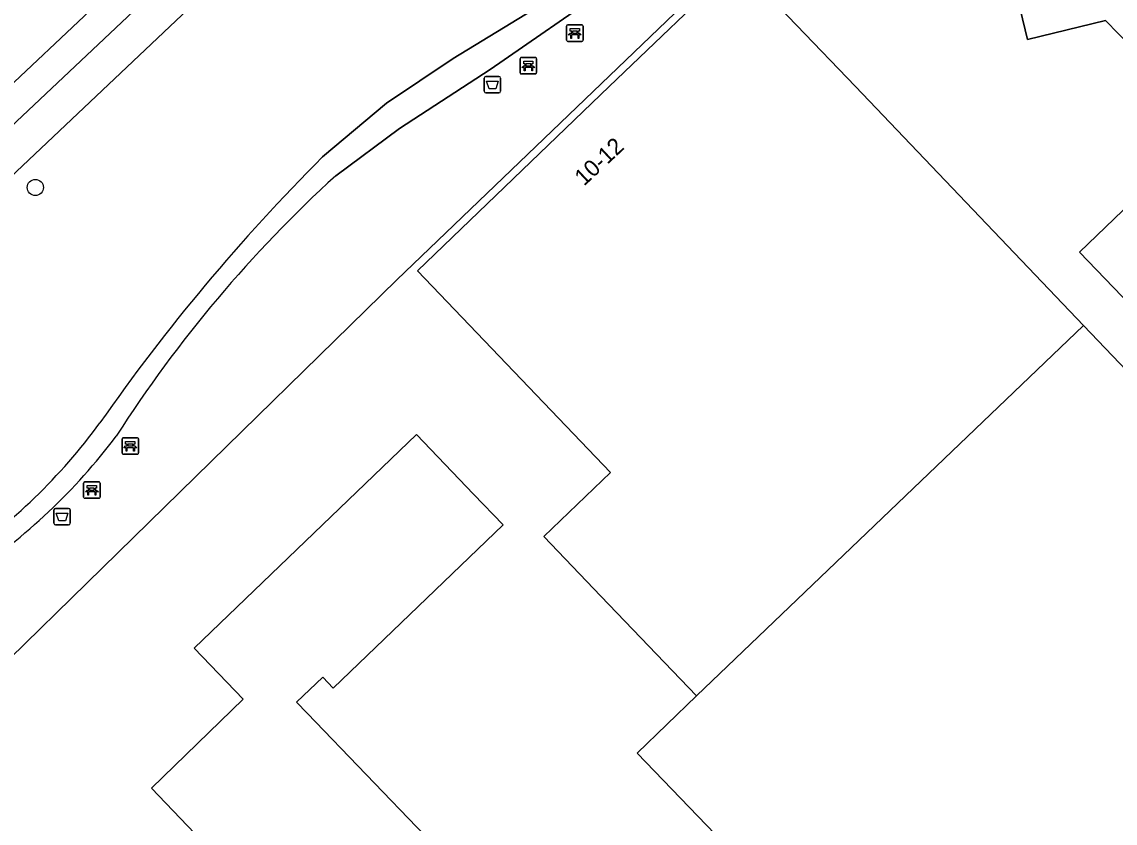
# Model space of a CAD drawing. Extents: x 156702 to 158052, y 387630 to 388992.
# Drawn here: x 157527.1 to 157593.4, y 388205.4 to 388253.9 of the extents above; entities that cross this region are included whole.
import ezdxf

# ---------------------------------------------------------------- set-up
doc = ezdxf.new("R2010")
doc.units = 0
for name, color, linetype in [('IMGEO_Afvalbak', 7, 'Continuous'), ('IMGEO_Bank', 7, 'Continuous'), ('IMGEO_Boom', 7, 'Continuous'), ('IMGEO_Erf', 7, 'Continuous'), ('IMGEO_Groenvoorziening', 7, 'Continuous'), ('IMGEO_Hek', 7, 'Continuous'), ('IMGEO_Pand', 7, 'Continuous'), ('IMGEO_Pand_nummerreeks', 7, 'Continuous'), ('IMGEO_Parkeervlak_open', 7, 'Continuous'), ('IMGEO_Voetpad_halfverhard', 7, 'Continuous'), ('IMGEO_Voetpad_open', 7, 'Continuous')]:
    doc.layers.add(name, color=color, linetype=linetype)

msp = doc.modelspace()

# ---------------------------------------------------------------- linework, layer by layer
at = {"layer": 'IMGEO_Afvalbak'}
for p, q in [((157555.123, 388249.714), (157555.123, 388250.514)), ((157555.123, 388250.514), (157555.123, 388249.714)), ((157555.223, 388250.614), (157556.013, 388250.614)), ((157556.013, 388250.614), (157555.223, 388250.614)), ((157556.113, 388250.514), (157556.113, 388249.714)), ((157556.113, 388249.714), (157556.113, 388250.514)), ((157556.013, 388249.614), (157555.223, 388249.614)), ((157555.223, 388249.614), (157556.013, 388249.614)), ((157529.032, 388223.535), (157529.032, 388224.335)), ((157529.032, 388224.335), (157529.032, 388223.535)), ((157529.132, 388224.435), (157529.922, 388224.435)), ((157529.922, 388224.435), (157529.132, 388224.435)), ((157530.022, 388224.335), (157530.022, 388223.535)), ((157530.022, 388223.535), (157530.022, 388224.335)), ((157529.922, 388223.435), (157529.132, 388223.435)), ((157529.132, 388223.435), (157529.922, 388223.435))]:
    msp.add_line(p, q, dxfattribs=at)
for points in [[(157555.266, 388250.328), (157555.97, 388250.328), (157555.821, 388249.858), (157555.415, 388249.858), (157555.266, 388250.328)], [(157529.175, 388224.149), (157529.879, 388224.149), (157529.73, 388223.679), (157529.324, 388223.679), (157529.175, 388224.149)]]:
    msp.add_lwpolyline(points, dxfattribs=at)
for centre, start, end in [((157555.223, 388250.514), 90, 180), ((157555.223, 388250.514), 90, 180), ((157556.013, 388250.514), 0, 90), ((157556.013, 388250.514), 360, 90), ((157555.223, 388249.714), 180, 270), ((157555.223, 388249.714), 180, 270), ((157556.013, 388249.714), 270, 0), ((157556.013, 388249.714), 270, 0), ((157529.132, 388224.335), 90, 180), ((157529.132, 388224.335), 90, 180), ((157529.922, 388224.335), 0, 90), ((157529.922, 388224.335), 360, 90), ((157529.132, 388223.535), 180, 270), ((157529.132, 388223.535), 180, 270), ((157529.922, 388223.535), 270, 0), ((157529.922, 388223.535), 270, 0)]:
    msp.add_arc(centre, 0.1, start, end, dxfattribs=at)
at = {"layer": 'IMGEO_Bank'}
for p, q in [((157560.191, 388253.742), (157561.032, 388253.742)), ((157561.032, 388253.742), (157560.191, 388253.742)), ((157560.116, 388252.817), (157560.116, 388253.658)), ((157560.116, 388253.658), (157560.116, 388252.817)), ((157560.813, 388253.14), (157560.42, 388253.14)), ((157560.425, 388253.248), (157560.425, 388253.354)), ((157560.469, 388253.354), (157560.469, 388253.248)), ((157560.757, 388253.36), (157560.475, 388253.36)), ((157560.475, 388253.242), (157560.757, 388253.242)), ((157560.763, 388253.248), (157560.763, 388253.354)), ((157560.807, 388253.354), (157560.807, 388253.248)), ((157561.116, 388253.667), (157561.116, 388252.826)), ((157561.116, 388252.826), (157561.116, 388253.667)), ((157561.041, 388252.742), (157560.2, 388252.742)), ((157560.2, 388252.742), (157561.041, 388252.742)), ((157557.374, 388251.765), (157558.215, 388251.765)), ((157558.215, 388251.765), (157557.374, 388251.765)), ((157557.299, 388250.84), (157557.299, 388251.681)), ((157557.299, 388251.681), (157557.299, 388250.84)), ((157557.996, 388251.163), (157557.603, 388251.163)), ((157557.608, 388251.271), (157557.608, 388251.377)), ((157557.652, 388251.377), (157557.652, 388251.271)), ((157557.94, 388251.383), (157557.658, 388251.383)), ((157557.658, 388251.265), (157557.94, 388251.265)), ((157557.946, 388251.271), (157557.946, 388251.377)), ((157557.99, 388251.377), (157557.99, 388251.271)), ((157558.299, 388251.69), (157558.299, 388250.849)), ((157558.299, 388250.849), (157558.299, 388251.69)), ((157558.224, 388250.765), (157557.383, 388250.765)), ((157557.383, 388250.765), (157558.224, 388250.765)), ((157533.163, 388227.79), (157533.163, 388228.631)), ((157533.163, 388228.631), (157533.163, 388227.79)), ((157533.238, 388228.715), (157534.079, 388228.715)), ((157534.079, 388228.715), (157533.238, 388228.715)), ((157534.163, 388228.64), (157534.163, 388227.799)), ((157534.163, 388227.799), (157534.163, 388228.64)), ((157533.86, 388228.113), (157533.467, 388228.113)), ((157533.472, 388228.221), (157533.472, 388228.327)), ((157533.516, 388228.327), (157533.516, 388228.221)), ((157533.804, 388228.333), (157533.522, 388228.333)), ((157533.522, 388228.215), (157533.804, 388228.215)), ((157533.81, 388228.221), (157533.81, 388228.327)), ((157533.854, 388228.327), (157533.854, 388228.221)), ((157534.088, 388227.715), (157533.247, 388227.715)), ((157533.247, 388227.715), (157534.088, 388227.715)), ((157530.835, 388225.117), (157530.835, 388225.958)), ((157530.835, 388225.958), (157530.835, 388225.117)), ((157530.91, 388226.042), (157531.751, 388226.042)), ((157531.751, 388226.042), (157530.91, 388226.042)), ((157531.835, 388225.967), (157531.835, 388225.126)), ((157531.835, 388225.126), (157531.835, 388225.967)), ((157531.532, 388225.44), (157531.139, 388225.44)), ((157531.144, 388225.548), (157531.144, 388225.654)), ((157531.188, 388225.654), (157531.188, 388225.548)), ((157531.476, 388225.66), (157531.194, 388225.66)), ((157531.194, 388225.542), (157531.476, 388225.542)), ((157531.482, 388225.548), (157531.482, 388225.654)), ((157531.526, 388225.654), (157531.526, 388225.548)), ((157531.76, 388225.042), (157530.919, 388225.042)), ((157530.919, 388225.042), (157531.76, 388225.042))]:
    msp.add_line(p, q, dxfattribs=at)
for points in [[(157560.363, 388253.14), (157560.221, 388253.14), (157560.333, 388253.242), (157560.419, 388253.242)], [(157560.419, 388253.36), (157560.333, 388253.36), (157560.333, 388253.521), (157560.896, 388253.521), (157560.896, 388253.36), (157560.813, 388253.36)], [(157560.413, 388253.133), (157560.413, 388252.926), (157560.37, 388252.926), (157560.37, 388253.133)], [(157560.813, 388253.242), (157560.896, 388253.242), (157561.008, 388253.14), (157560.869, 388253.14)], [(157560.863, 388253.133), (157560.863, 388252.926), (157560.819, 388252.926), (157560.819, 388253.133)], [(157557.546, 388251.163), (157557.404, 388251.163), (157557.516, 388251.265), (157557.602, 388251.265)], [(157557.602, 388251.383), (157557.516, 388251.383), (157557.516, 388251.544), (157558.079, 388251.544), (157558.079, 388251.383), (157557.996, 388251.383)], [(157557.596, 388251.156), (157557.596, 388250.949), (157557.553, 388250.949), (157557.553, 388251.156)], [(157557.996, 388251.265), (157558.079, 388251.265), (157558.191, 388251.163), (157558.052, 388251.163)], [(157558.046, 388251.156), (157558.046, 388250.949), (157558.002, 388250.949), (157558.002, 388251.156)], [(157533.41, 388228.113), (157533.268, 388228.113), (157533.38, 388228.215), (157533.466, 388228.215)], [(157533.466, 388228.333), (157533.38, 388228.333), (157533.38, 388228.494), (157533.943, 388228.494), (157533.943, 388228.333), (157533.86, 388228.333)], [(157533.46, 388228.106), (157533.46, 388227.899), (157533.417, 388227.899), (157533.417, 388228.106)], [(157533.86, 388228.215), (157533.943, 388228.215), (157534.055, 388228.113), (157533.916, 388228.113)], [(157533.91, 388228.106), (157533.91, 388227.899), (157533.866, 388227.899), (157533.866, 388228.106)], [(157531.082, 388225.44), (157530.94, 388225.44), (157531.052, 388225.542), (157531.138, 388225.542)], [(157531.138, 388225.66), (157531.052, 388225.66), (157531.052, 388225.821), (157531.615, 388225.821), (157531.615, 388225.66), (157531.532, 388225.66)], [(157531.132, 388225.433), (157531.132, 388225.226), (157531.089, 388225.226), (157531.089, 388225.433)], [(157531.532, 388225.542), (157531.615, 388225.542), (157531.727, 388225.44), (157531.588, 388225.44)], [(157531.582, 388225.433), (157531.582, 388225.226), (157531.538, 388225.226), (157531.538, 388225.433)]]:
    msp.add_lwpolyline(points, dxfattribs=at)
for centre, radius, start, end in [((157560.194, 388253.664), 0.0779, 92.4484, 184.28452), ((157560.194, 388253.664), 0.0779, 92.4484, 184.28452), ((157561.038, 388253.664), 0.0779, 2.4484, 94.28452), ((157561.038, 388253.664), 0.0779, 2.4484, 94.28452), ((157560.363, 388253.133), 0.00671, 2.89567, 87.10433), ((157560.42, 388253.133), 0.00671, 92.89567, 177.10433), ((157560.418, 388253.353), 0.00671, 2.89567, 87.10433), ((157560.418, 388253.249), 0.00671, 272.89567, 357.10433), ((157560.475, 388253.353), 0.00671, 92.89567, 177.10433), ((157560.475, 388253.249), 0.00671, 182.89567, 267.10433), ((157560.757, 388253.353), 0.00671, 2.89567, 87.10433), ((157560.757, 388253.249), 0.00671, 272.89567, 357.10433), ((157560.814, 388253.353), 0.00671, 92.89567, 177.10433), ((157560.814, 388253.249), 0.00671, 182.89567, 267.10433), ((157560.812, 388253.133), 0.00671, 2.89567, 87.10433), ((157560.869, 388253.133), 0.00671, 92.89567, 177.10433), ((157560.194, 388252.82), 0.0779, 182.4484, 274.28452), ((157560.194, 388252.82), 0.0779, 182.4484, 274.28452), ((157561.038, 388252.82), 0.0779, 272.4484, 4.28452), ((157561.038, 388252.82), 0.0779, 272.4484, 4.28452), ((157557.377, 388251.687), 0.0779, 92.4484, 184.28452), ((157557.377, 388251.687), 0.0779, 92.4484, 184.28452), ((157558.221, 388251.687), 0.0779, 2.4484, 94.28452), ((157558.221, 388251.687), 0.0779, 2.4484, 94.28452), ((157557.546, 388251.156), 0.00671, 2.89567, 87.10433), ((157557.603, 388251.156), 0.00671, 92.89567, 177.10433), ((157557.601, 388251.376), 0.00671, 2.89567, 87.10433), ((157557.601, 388251.272), 0.00671, 272.89567, 357.10433), ((157557.658, 388251.376), 0.00671, 92.89567, 177.10433), ((157557.658, 388251.272), 0.00671, 182.89567, 267.10433), ((157557.94, 388251.376), 0.00671, 2.89567, 87.10433), ((157557.94, 388251.272), 0.00671, 272.89567, 357.10433), ((157557.997, 388251.376), 0.00671, 92.89567, 177.10433), ((157557.997, 388251.272), 0.00671, 182.89567, 267.10433), ((157557.995, 388251.156), 0.00671, 2.89567, 87.10433), ((157558.052, 388251.156), 0.00671, 92.89567, 177.10433), ((157557.377, 388250.843), 0.0779, 182.4484, 274.28452), ((157557.377, 388250.843), 0.0779, 182.4484, 274.28452), ((157558.221, 388250.843), 0.0779, 272.4484, 4.28452), ((157558.221, 388250.843), 0.0779, 272.4484, 4.28452), ((157533.241, 388228.637), 0.0779, 92.4484, 184.28452), ((157533.241, 388228.637), 0.0779, 92.4484, 184.28452), ((157534.085, 388228.637), 0.0779, 2.4484, 94.28452), ((157534.085, 388228.637), 0.0779, 2.4484, 94.28452), ((157533.41, 388228.106), 0.00671, 2.89567, 87.10433), ((157533.467, 388228.106), 0.00671, 92.89567, 177.10433), ((157533.465, 388228.326), 0.00671, 2.89567, 87.10433), ((157533.465, 388228.222), 0.00671, 272.89567, 357.10433), ((157533.522, 388228.326), 0.00671, 92.89567, 177.10433), ((157533.522, 388228.222), 0.00671, 182.89567, 267.10433), ((157533.804, 388228.326), 0.00671, 2.89567, 87.10433), ((157533.804, 388228.222), 0.00671, 272.89567, 357.10433), ((157533.861, 388228.326), 0.00671, 92.89567, 177.10433), ((157533.861, 388228.222), 0.00671, 182.89567, 267.10433), ((157533.859, 388228.106), 0.00671, 2.89567, 87.10433), ((157533.916, 388228.106), 0.00671, 92.89567, 177.10433), ((157533.241, 388227.793), 0.0779, 182.4484, 274.28452), ((157533.241, 388227.793), 0.0779, 182.4484, 274.28452), ((157534.085, 388227.793), 0.0779, 272.4484, 4.28452), ((157534.085, 388227.793), 0.0779, 272.4484, 4.28452), ((157530.913, 388225.964), 0.0779, 92.4484, 184.28452), ((157530.913, 388225.964), 0.0779, 92.4484, 184.28452), ((157531.757, 388225.964), 0.0779, 2.4484, 94.28452), ((157531.757, 388225.964), 0.0779, 2.4484, 94.28452), ((157531.082, 388225.433), 0.00671, 2.89567, 87.10433), ((157531.139, 388225.433), 0.00671, 92.89567, 177.10433), ((157531.137, 388225.653), 0.00671, 2.89567, 87.10433), ((157531.137, 388225.549), 0.00671, 272.89567, 357.10433), ((157531.194, 388225.653), 0.00671, 92.89567, 177.10433), ((157531.194, 388225.549), 0.00671, 182.89567, 267.10433), ((157531.476, 388225.653), 0.00671, 2.89567, 87.10433), ((157531.476, 388225.549), 0.00671, 272.89567, 357.10433), ((157531.533, 388225.653), 0.00671, 92.89567, 177.10433), ((157531.533, 388225.549), 0.00671, 182.89567, 267.10433), ((157531.531, 388225.433), 0.00671, 2.89567, 87.10433), ((157531.588, 388225.433), 0.00671, 92.89567, 177.10433), ((157530.913, 388225.12), 0.0779, 182.4484, 274.28452), ((157530.913, 388225.12), 0.0779, 182.4484, 274.28452), ((157531.757, 388225.12), 0.0779, 272.4484, 4.28452), ((157531.757, 388225.12), 0.0779, 272.4484, 4.28452)]:
    msp.add_arc(centre, radius, start, end, dxfattribs=at)
at = {"layer": 'IMGEO_Boom'}
msp.add_circle((157527.908, 388243.888), 0.489, dxfattribs=at)
at = {"layer": 'IMGEO_Erf'}
msp.add_lwpolyline([(157658.038, 388128.535), (157625.935, 388161.878), (157607.282, 388185.621), (157608.898, 388187.206), (157610.099, 388188.384), (157623.93, 388201.777), (157623.255, 388202.443), (157620.192, 388205.465), (157645.529, 388228.506), (157632.467, 388250), (157610.903, 388285.301), (157607.916, 388284.647), (157606.015, 388284.23), (157605.995, 388284.226), (157600.361, 388282.974), (157600.248, 388282.949), (157584.393, 388279.471), (157583.238, 388279.218), (157580.396, 388278.594), (157580.164, 388267.028), (157570.163, 388257.803), (157549.83, 388238.291), (157521.638, 388210.734)], dxfattribs=at)
for points in [[(157591.219, 388239.966), (157599.102, 388247.548), (157592.797, 388254.003), (157588.066, 388252.862), (157586.271, 388260.31), (157590.094, 388261.231), (157588.851, 388266.39), (157597.602, 388268.521), (157598.88, 388267.785), (157600.973, 388259.006), (157600.643, 388258.927), (157605.602, 388253.76), (157605.847, 388253.996), (157609.69, 388250), (157619.698, 388239.595), (157623.892, 388243.616), (157618.243, 388253.459), (157618.611, 388256.134), (157624.034, 388261.314), (157630.532, 388249.983), (157640.873, 388231.95), (157619.052, 388211.029)], [(157584.886, 388188.316), (157564.394, 388209.598), (157567.99, 388213.072), (157562.196, 388219.112), (157558.734, 388222.72), (157562.775, 388226.601), (157551.074, 388238.835), (157562.705, 388250), (157570.484, 388257.467), (157577.622, 388250), (157591.461, 388235.522), (157612.045, 388213.988), (157596.348, 388199.15)], [(157545.965, 388213.543), (157545.335, 388214.2), (157543.747, 388212.677), (157544.379, 388212.022), (157551.546, 388204.59), (157548.388, 388201.538), (157548.939, 388200.958), (157548.07, 388200.135), (157547.532, 388200.697), (157544.359, 388197.674), (157540.74, 388201.439), (157538.454, 388203.818), (157534.94, 388207.473), (157540.5, 388212.859), (157537.541, 388215.969), (157551.018, 388228.911), (157554.477, 388225.3), (157556.264, 388223.433)]]:
    msp.add_lwpolyline(points, close=True, dxfattribs=at)
at = {"layer": 'IMGEO_Groenvoorziening'}
for points in [[(157545.322, 388245.734), (157549.198, 388248.998), (157553.246, 388251.711), (157562.026, 388257.076), (157562.167, 388257.165), (157555, 388267.932)], [(157523.901, 388220.394), (157520.769, 388218.199), (157519.178, 388217.192), (157517.55, 388216.231), (157515.912, 388215.58), (157514.139, 388214.694), (157514.488, 388214.333), (157515.322, 388213.47), (157517.815, 388210.892), (157518.075, 388210.62), (157521.476, 388210.646), (157521.638, 388210.734), (157549.83, 388238.291), (157570.163, 388257.803)], [(157535.621, 388256.258), (157505.877, 388228.213)], [(157562.747, 388256.067), (157555.487, 388251.042), (157549.984, 388247.466), (157546.12, 388244.598)], [(157507.77, 388226.91), (157537.177, 388254.693)], [(157537.177, 388254.693), (157507.77, 388226.91)]]:
    msp.add_lwpolyline(points, dxfattribs=at)
for centre, radius, start, end in [((157629.29, 388161.704), 118.793, 134.97865, 145.13605), ((157599.418, 388186.173), 79.083, 132.37264, 147.37752), ((157503.225, 388250.587), 35.464, 304.27835, 323.73378), ((157503.526, 388250.897), 36.682, 303.74136, 322.97189)]:
    msp.add_arc(centre, radius, start, end, dxfattribs=at)
at = {"layer": 'IMGEO_Hek'}
msp.add_lwpolyline([(157570.163, 388257.803), (157549.83, 388238.291), (157521.638, 388210.734)], dxfattribs=at)
at = {"layer": 'IMGEO_Pand'}
for points in [[(157630.532, 388249.983), (157624.034, 388261.314), (157618.611, 388256.134), (157618.243, 388253.459), (157623.892, 388243.616), (157619.698, 388239.595), (157609.69, 388250), (157605.847, 388253.996), (157605.602, 388253.76), (157600.643, 388258.927), (157600.973, 388259.006), (157598.88, 388267.785), (157597.602, 388268.521), (157588.851, 388266.39), (157590.094, 388261.231), (157586.271, 388260.31), (157588.066, 388252.862), (157592.797, 388254.003), (157599.102, 388247.548), (157591.219, 388239.966), (157619.052, 388211.029), (157640.873, 388231.95)], [(157567.99, 388213.072), (157591.461, 388235.522), (157577.622, 388250), (157570.484, 388257.467), (157562.705, 388250), (157551.074, 388238.835), (157562.775, 388226.601), (157558.734, 388222.72), (157562.196, 388219.112)], [(157567.99, 388213.072), (157564.394, 388209.598), (157584.886, 388188.316), (157596.348, 388199.15), (157612.045, 388213.988), (157591.461, 388235.522)], [(157538.454, 388203.818), (157540.74, 388201.439), (157544.359, 388197.674), (157547.532, 388200.697), (157548.07, 388200.135), (157548.939, 388200.958), (157548.388, 388201.538), (157551.546, 388204.59), (157544.379, 388212.022), (157543.747, 388212.677), (157545.335, 388214.2), (157545.965, 388213.543), (157556.264, 388223.433), (157554.477, 388225.3), (157551.018, 388228.911), (157537.541, 388215.969), (157540.5, 388212.859), (157534.94, 388207.473)]]:
    msp.add_lwpolyline(points, close=True, dxfattribs=at)
at = {"layer": 'IMGEO_Parkeervlak_open'}
msp.add_lwpolyline([(157511.07, 388235.613), (157534.411, 388257.628)], dxfattribs=at)
at = {"layer": 'IMGEO_Voetpad_halfverhard'}
for points in [[(157562.167, 388257.165), (157562.026, 388257.076), (157553.246, 388251.711), (157549.198, 388248.998), (157545.322, 388245.734)], [(157549.984, 388247.466), (157555.487, 388251.042), (157562.747, 388256.067)], [(157546.12, 388244.598), (157549.984, 388247.466)]]:
    msp.add_lwpolyline(points, dxfattribs=at)
for centre, radius, start, end in [((157629.29, 388161.704), 118.793, 134.97865, 145.13605), ((157599.418, 388186.173), 79.083, 132.37264, 147.37752), ((157503.225, 388250.587), 35.464, 304.27835, 323.73378), ((157503.526, 388250.897), 36.682, 303.74136, 322.97189)]:
    msp.add_arc(centre, radius, start, end, dxfattribs=at)
at = {"layer": 'IMGEO_Voetpad_open'}
for points in [[(157534.411, 388257.628), (157511.07, 388235.613)], [(157505.877, 388228.213), (157535.621, 388256.258)]]:
    msp.add_lwpolyline(points, dxfattribs=at)

# ---------------------------------------------------------------- texts
at = {"layer": 'IMGEO_Pand_nummerreeks'}
msp.add_text('10-12', height=1, rotation=42.99921, dxfattribs=at).set_placement((157561.171, 388243.935))

doc.saveas('drawing.dxf')
